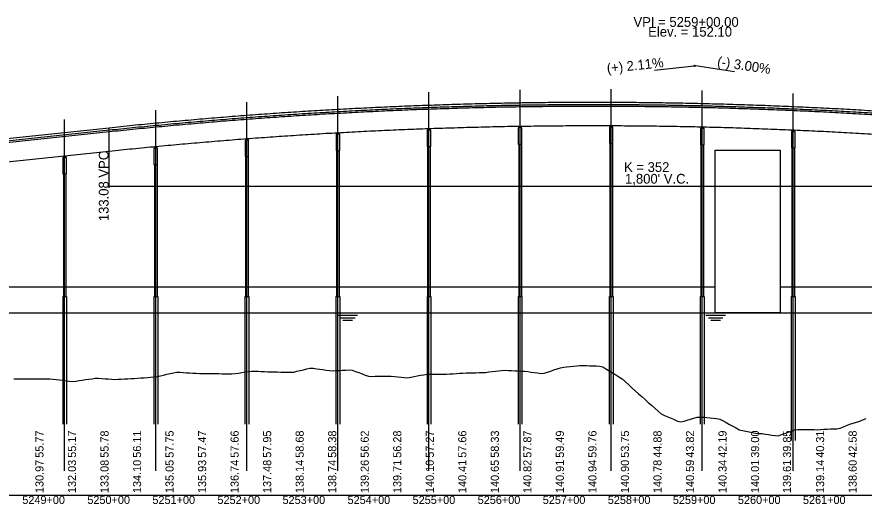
# Model space of a CAD drawing. Extents: x 2121671 to 2169879, y 557274 to 599957.
# Drawn here: x 2154426 to 2155728, y 579173 to 579923 of the extents above; entities that cross this region are included whole.
import ezdxf

# ---------------------------------------------------------------- set-up
doc = ezdxf.new("R2010")
doc.units = 0
for name, color, linetype in [('BR_CENTER LINES', 7, 'Continuous'), ('BR_CONCRETE', 7, 'Continuous'), ('BR_DETAILS', 7, 'Continuous'), ('BR_PRESTRESSED BEAM', 7, 'Continuous'), ('RD_DDB_GradeTX', 7, 'Continuous'), ('RD_DDB_Profile_Elev', 7, 'Continuous'), ('RD_DDB_Profile_EX', 7, 'Continuous'), ('RD_DDB_Profile_Lbl', 7, 'Continuous'), ('RD_DDB_Profile_PR', 7, 'Continuous'), ('RD_DDB_StaTX', 7, 'Continuous'), ('RD_DDB_StripGrade', 7, 'Continuous'), ('RD_DDB_VCLbl', 7, 'Continuous'), ('RD_GPK_Profile_Cell', 7, 'Continuous')]:
    doc.layers.add(name, color=color, linetype=linetype)

msp = doc.modelspace()

# ---------------------------------------------------------------- linework, layer by layer
at = {"layer": 'BR_CENTER LINES'}
for p, q in [((2155339.4, 579224.3), (2155339.4, 579811.5)), ((2154919.4, 579224.3), (2154919.4, 579800.6)), ((2155059.4, 579224.3), (2155059.4, 579807)), ((2155199.4, 579224.3), (2155199.4, 579810.6)), ((2155479.4, 579224.3), (2155479.4, 579809.5)), ((2155619.4, 579224.3), (2155619.4, 579804.8)), ((2154779.4, 579224.3), (2154779.4, 579791.4)), ((2154639.4, 579224.3), (2154639.4, 579779.4)), ((2154499.4, 579224.3), (2154499.4, 579765))]:
    msp.add_line(p, q, dxfattribs=at)
at = {"layer": 'BR_CONCRETE'}
for p, q in [((2154274.9, 579717.8), (2154567.9, 579748.7)), ((2155057.4, 579723.4), (2155057.4, 579492.4)), ((2155061.4, 579723.4), (2155061.4, 579492.4)), ((2155197.4, 579727.1), (2155197.4, 579492.4)), ((2155201.4, 579727.1), (2155201.4, 579492.4)), ((2155337.4, 579727.9), (2155337.4, 579492.4)), ((2155341.4, 579727.9), (2155341.4, 579492.4)), ((2155477.4, 579726), (2155477.4, 579492.4)), ((2155481.4, 579726), (2155481.4, 579492.4)), ((2155617.4, 579721.2), (2155617.4, 579492.4)), ((2155621.4, 579721.2), (2155621.4, 579492.4)), ((2154777.4, 579707.8), (2154777.4, 579492.4)), ((2154781.4, 579707.8), (2154781.4, 579492.4)), ((2154917.4, 579717), (2154917.4, 579492.4)), ((2154921.4, 579717), (2154921.4, 579492.4)), ((2154637.4, 579695.8), (2154637.4, 579492.4)), ((2154641.4, 579695.8), (2154641.4, 579492.4)), ((2154497.4, 579681.3), (2154497.4, 579492.4)), ((2154501.4, 579681.3), (2154501.4, 579492.4)), ((2154496.4, 579492.4), (2154496.4, 579296.1)), ((2154496.4, 579492.4), (2154502.4, 579492.4)), ((2154502.4, 579492.4), (2154502.4, 579296.1)), ((2154636.4, 579492.4), (2154636.4, 579296.1)), ((2154636.4, 579492.4), (2154642.4, 579492.4)), ((2154642.4, 579492.4), (2154642.4, 579296.1)), ((2154776.4, 579492.4), (2154776.4, 579296.1)), ((2154776.4, 579492.4), (2154782.4, 579492.4)), ((2154782.4, 579492.4), (2154782.4, 579296.1)), ((2154916.4, 579492.4), (2154916.4, 579296.1)), ((2154916.4, 579492.4), (2154922.4, 579492.4)), ((2154922.4, 579492.4), (2154922.4, 579296.1)), ((2155056.4, 579492.4), (2155056.4, 579296.1)), ((2155056.4, 579492.4), (2155062.4, 579492.4)), ((2155062.4, 579492.4), (2155062.4, 579296.1)), ((2155196.4, 579492.4), (2155196.4, 579296.1)), ((2155196.4, 579492.4), (2155202.4, 579492.4)), ((2155202.4, 579492.4), (2155202.4, 579296.1)), ((2155336.4, 579492.4), (2155336.4, 579296.1)), ((2155336.4, 579492.4), (2155342.4, 579492.4)), ((2155342.4, 579492.4), (2155342.4, 579296.1)), ((2155476.4, 579492.4), (2155476.4, 579296.1)), ((2155476.4, 579492.4), (2155482.4, 579492.4)), ((2155482.4, 579492.4), (2155482.4, 579296.1)), ((2155616.4, 579492.4), (2155616.4, 579271.3)), ((2155616.4, 579492.4), (2155622.4, 579492.4)), ((2155622.4, 579492.4), (2155622.4, 579271.3))]:
    msp.add_line(p, q, dxfattribs=at)
for points in [[(2155056.7, 579723.4), (2155062.2, 579723.4), (2155062.2, 579748.4), (2155056.7, 579748.4)], [(2155196.7, 579727.1), (2155202.2, 579727.1), (2155202.2, 579752.1), (2155196.7, 579752.1)], [(2155336.7, 579727.9), (2155342.2, 579727.9), (2155342.2, 579752.9), (2155336.7, 579752.9)], [(2155476.7, 579726), (2155482.2, 579726), (2155482.2, 579751), (2155476.7, 579751)], [(2154916.7, 579717), (2154922.2, 579717), (2154922.2, 579742), (2154916.7, 579742)], [(2155616.7, 579721.2), (2155622.2, 579721.2), (2155622.2, 579746.2), (2155616.7, 579746.2)], [(2154636.7, 579695.8), (2154642.2, 579695.8), (2154642.2, 579720.8), (2154636.7, 579720.8)], [(2154776.7, 579707.8), (2154782.2, 579707.8), (2154782.2, 579732.8), (2154776.7, 579732.8)], [(2154496.7, 579681.3), (2154502.2, 579681.3), (2154502.2, 579706.3), (2154496.7, 579706.3)]]:
    msp.add_lwpolyline(points, close=True, dxfattribs=at)
msp.add_spline([(2154567.9, 579748.7), (2154603.9, 579752.4), (2154639.9, 579755.9), (2154675.9, 579759.3), (2154711.9, 579762.4), (2154747.9, 579765.4), (2154783.9, 579768.2), (2154819.9, 579770.8), (2154855.9, 579773.2), (2154891.9, 579775.5), (2154927.9, 579777.5), (2154963.9, 579779.4), (2154999.9, 579781.1), (2155035.9, 579782.6), (2155071.9, 579783.9), (2155107.9, 579785), (2155143.9, 579786), (2155179.9, 579786.8), (2155215.9, 579787.3), (2155251.9, 579787.7), (2155287.9, 579787.9), (2155323.9, 579788), (2155359.9, 579787.8), (2155395.9, 579787.5), (2155431.9, 579787), (2155467.9, 579786.3), (2155503.9, 579785.4), (2155539.9, 579784.3), (2155575.9, 579783), (2155611.9, 579781.6), (2155647.9, 579780), (2155683.9, 579778.2), (2155719.9, 579776.2), (2155755.9, 579774), (2155791.9, 579771.6), (2155827.9, 579769.1), (2155863.9, 579766.3), (2155899.9, 579763.4), (2155935.9, 579760.3), (2155971.9, 579757), (2156007.9, 579753.6), (2156043.9, 579749.9), (2156079.9, 579746.1), (2156115.9, 579742.1), (2156151.9, 579737.9), (2156187.9, 579733.5), (2156223.9, 579728.9), (2156259.9, 579724.1), (2156295.9, 579719.2), (2156331.9, 579714.1), (2156367.9, 579708.8)], degree=3, dxfattribs=at)
at = {"layer": 'BR_DETAILS'}
for points in [[(2155057.9, 579750.9), (2155058.9, 579750.9), (2155058.9, 579748.4), (2155057.9, 579748.4)], [(2155059.9, 579750.9), (2155060.9, 579750.9), (2155060.9, 579748.4), (2155059.9, 579748.4)], [(2155197.9, 579754.6), (2155198.9, 579754.6), (2155198.9, 579752.1), (2155197.9, 579752.1)], [(2155199.9, 579754.6), (2155200.9, 579754.6), (2155200.9, 579752.1), (2155199.9, 579752.1)], [(2155337.9, 579755.4), (2155338.9, 579755.4), (2155338.9, 579752.9), (2155337.9, 579752.9)], [(2155339.9, 579755.4), (2155340.9, 579755.4), (2155340.9, 579752.9), (2155339.9, 579752.9)], [(2155477.9, 579753.5), (2155478.9, 579753.5), (2155478.9, 579751), (2155477.9, 579751)], [(2155479.9, 579753.5), (2155480.9, 579753.5), (2155480.9, 579751), (2155479.9, 579751)], [(2155617.9, 579748.7), (2155618.9, 579748.7), (2155618.9, 579746.2), (2155617.9, 579746.2)], [(2155619.9, 579748.7), (2155620.9, 579748.7), (2155620.9, 579746.2), (2155619.9, 579746.2)], [(2154777.9, 579735.3), (2154778.9, 579735.3), (2154778.9, 579732.8), (2154777.9, 579732.8)], [(2154779.9, 579735.3), (2154780.9, 579735.3), (2154780.9, 579732.8), (2154779.9, 579732.8)], [(2154917.9, 579744.5), (2154918.9, 579744.5), (2154918.9, 579742), (2154917.9, 579742)], [(2154919.9, 579744.5), (2154920.9, 579744.5), (2154920.9, 579742), (2154919.9, 579742)], [(2154637.9, 579723.3), (2154638.9, 579723.3), (2154638.9, 579720.8), (2154637.9, 579720.8)], [(2154639.9, 579723.3), (2154640.9, 579723.3), (2154640.9, 579720.8), (2154639.9, 579720.8)], [(2154497.9, 579708.8), (2154498.9, 579708.8), (2154498.9, 579706.3), (2154497.9, 579706.3)], [(2154499.9, 579708.8), (2154500.9, 579708.8), (2154500.9, 579706.3), (2154499.9, 579706.3)]]:
    msp.add_lwpolyline(points, close=True, dxfattribs=at)
at = {"layer": 'BR_PRESTRESSED BEAM'}
for p, q in [((2154274.9, 579715.3), (2154567.9, 579746.2)), ((2154359.4, 579694.2), (2154567.9, 579716.2))]:
    msp.add_line(p, q, dxfattribs=at)
for points in [[(2154567.9, 579746.2), (2154603.9, 579749.9), (2154639.9, 579753.4), (2154675.9, 579756.8), (2154711.9, 579759.9), (2154747.9, 579762.9), (2154783.9, 579765.7), (2154819.9, 579768.3), (2154855.9, 579770.7), (2154891.9, 579773), (2154927.9, 579775), (2154963.9, 579776.9), (2154999.9, 579778.6), (2155035.9, 579780.1), (2155071.9, 579781.4), (2155107.9, 579782.5), (2155143.9, 579783.5), (2155179.9, 579784.3), (2155215.9, 579784.8), (2155251.9, 579785.2), (2155287.9, 579785.4), (2155323.9, 579785.5), (2155359.9, 579785.3), (2155395.9, 579785), (2155431.9, 579784.5), (2155467.9, 579783.8), (2155503.9, 579782.9), (2155539.9, 579781.8), (2155575.9, 579780.5), (2155611.9, 579779.1), (2155647.9, 579777.5), (2155683.9, 579775.7), (2155719.9, 579773.7), (2155755.9, 579771.5), (2155791.9, 579769.1), (2155827.9, 579766.6), (2155863.9, 579763.8), (2155899.9, 579760.9), (2155935.9, 579757.8), (2155971.9, 579754.5), (2156007.9, 579751.1), (2156043.9, 579747.4), (2156079.9, 579743.6), (2156115.9, 579739.6), (2156151.9, 579735.4), (2156187.9, 579731), (2156223.9, 579726.4), (2156259.9, 579721.6), (2156295.9, 579716.7), (2156331.9, 579711.6), (2156367.9, 579706.3)], [(2154567.9, 579716.2), (2154603.9, 579719.9), (2154639.9, 579723.4), (2154675.9, 579726.8), (2154711.9, 579729.9), (2154747.9, 579732.9), (2154783.9, 579735.7), (2154819.9, 579738.3), (2154855.9, 579740.7), (2154891.9, 579743), (2154927.9, 579745), (2154963.9, 579746.9), (2154999.9, 579748.6), (2155035.9, 579750.1), (2155071.9, 579751.4), (2155107.9, 579752.5), (2155143.9, 579753.5), (2155179.9, 579754.3), (2155215.9, 579754.8), (2155251.9, 579755.2), (2155287.9, 579755.4), (2155323.9, 579755.5), (2155359.9, 579755.3), (2155395.9, 579755), (2155431.9, 579754.5), (2155467.9, 579753.8), (2155503.9, 579752.9), (2155539.9, 579751.8), (2155575.9, 579750.5), (2155611.9, 579749.1), (2155647.9, 579747.5), (2155683.9, 579745.7), (2155719.9, 579743.7), (2155755.9, 579741.5), (2155791.9, 579739.1), (2155827.9, 579736.6), (2155863.9, 579733.8), (2155899.9, 579730.9), (2155935.9, 579727.8), (2155971.9, 579724.5), (2156007.9, 579721.1), (2156043.9, 579717.4), (2156079.9, 579713.6), (2156115.9, 579709.6), (2156151.9, 579705.4), (2156187.9, 579701), (2156223.9, 579696.4), (2156259.9, 579691.6), (2156295.9, 579686.7), (2156331.9, 579681.6), (2156367.9, 579676.3)]]:
    msp.add_spline(points, degree=3, dxfattribs=at)
at = {"layer": 'RD_DDB_GradeTX'}
for p, q in [((2155406.3, 579840.8), (2155466.9, 579847.2)), ((2155529.2, 579838.1), (2155468.9, 579847.2))]:
    msp.add_line(p, q, dxfattribs=at)
msp.add_circle((2155467.9, 579847.3), 1, dxfattribs=at)
at = {"layer": 'RD_DDB_Profile_Elev'}
for p, q in [((2151922.4, 579507.4), (2155499.4, 579507.4)), ((2155599.4, 579507.4), (2156363.2, 579507.4)), ((2151953.5, 579467.4), (2156316.6, 579467.4)), ((2154919.6, 579463.7), (2154949.6, 579463.7)), ((2154923.4, 579459.9), (2154945.9, 579459.9)), ((2155485.2, 579463.7), (2155515.2, 579463.7)), ((2155488.9, 579459.9), (2155511.4, 579459.9)), ((2154927.1, 579456.2), (2154942.1, 579456.2)), ((2155492.7, 579456.2), (2155507.7, 579456.2))]:
    msp.add_line(p, q, dxfattribs=at)
msp.add_lwpolyline([(2155499.4, 579717.4), (2155599.4, 579717.4), (2155599.4, 579467.4), (2155499.4, 579467.4)], close=True, dxfattribs=at)
at = {"layer": 'RD_DDB_Profile_EX'}
for points in [[(2154721.5, 579374.1), (2154726.5, 579374), (2154731.5, 579374.1), (2154736.5, 579374), (2154741.5, 579373.9), (2154746.5, 579373.8), (2154751.5, 579373.7), (2154756.5, 579373.6), (2154761.5, 579374.1), (2154766.5, 579374.9), (2154771.5, 579375.7), (2154776.5, 579376.5), (2154781.5, 579377.3), (2154786.5, 579378), (2154791.5, 579377.7), (2154796.5, 579377.5), (2154801.5, 579377.2), (2154806.5, 579377), (2154811.5, 579376.8), (2154816.5, 579376.6), (2154821.5, 579376.5), (2154826.5, 579376.5), (2154831.5, 579376.4), (2154836.5, 579376.3), (2154841.5, 579376.3), (2154846.5, 579376.2), (2154851.5, 579376.3), (2154856.5, 579377.5), (2154861.5, 579378.7), (2154866.5, 579379.9), (2154871.5, 579381.1), (2154876.5, 579382.3), (2154881.5, 579382.2), (2154886.5, 579381.5), (2154891.5, 579380.8), (2154896.5, 579380.2), (2154901.5, 579379.5), (2154906.5, 579378.8), (2154911.5, 579378.3), (2154916.5, 579378.6), (2154921.5, 579378.9), (2154926.5, 579379.2), (2154931.5, 579379.5), (2154936.5, 579379.8), (2154941.5, 579379.2), (2154946.5, 579377.4), (2154951.5, 579375.5), (2154956.5, 579373.7), (2154961.5, 579371.8), (2154966.5, 579370), (2154971.5, 579369.8), (2154976.5, 579369.9), (2154981.5, 579370), (2154986.5, 579370), (2154991.5, 579370.1), (2154996.5, 579370.2), (2155001.5, 579369.9), (2155006.5, 579369.4), (2155011.5, 579368.9), (2155016.5, 579368.4), (2155021.5, 579367.8), (2155026.5, 579367.5), (2155031.5, 579368.5), (2155036.5, 579369.4), (2155041.5, 579370.4), (2155046.5, 579371.4), (2155051.5, 579372.3), (2155056.5, 579373.3), (2155061.5, 579373.2), (2155066.5, 579373.2), (2155071.5, 579373.1), (2155076.5, 579373.1), (2155081.5, 579373), (2155086.5, 579373.1), (2155091.5, 579373.4), (2155096.5, 579373.7), (2155101.5, 579374.1), (2155106.5, 579374.5), (2155111.5, 579374.8), (2155116.5, 579375.1), (2155121.5, 579375.2), (2155126.5, 579375.3), (2155131.5, 579375.4), (2155136.5, 579375.5), (2155141.5, 579375.6), (2155146.5, 579375.9), (2155151.5, 579376.5), (2155156.5, 579377.1), (2155161.5, 579377.7), (2155166.5, 579378.3), (2155171.5, 579378.9), (2155176.5, 579379.1), (2155181.5, 579378.9), (2155186.5, 579378.7), (2155191.5, 579378.5), (2155196.5, 579378.2), (2155201.5, 579378), (2155206.5, 579377.7), (2155211.5, 579377.1), (2155216.5, 579376.4), (2155221.5, 579375.7)], [(2155221.5, 579375.7), (2155226.5, 579375), (2155231.5, 579374.3), (2155236.5, 579374.6), (2155241.5, 579376.2), (2155246.5, 579377.9), (2155251.5, 579379.6), (2155256.5, 579381.2), (2155261.5, 579382.9), (2155266.5, 579384.1), (2155271.5, 579384.6), (2155276.5, 579385.1), (2155281.5, 579385.6), (2155286.5, 579386.1), (2155291.5, 579386.6), (2155296.5, 579386.7), (2155301.5, 579386.5), (2155306.5, 579386.2), (2155311.5, 579386), (2155316.5, 579385.7), (2155321.5, 579385.4), (2155326.5, 579384.2), (2155331.5, 579381.2), (2155336.5, 579378.2), (2155341.5, 579375.2), (2155346.5, 579372.2), (2155351.5, 579369.2), (2155356.5, 579366.1), (2155361.5, 579361.5), (2155366.5, 579356.9), (2155371.5, 579352.3), (2155376.5, 579347.7), (2155381.5, 579343.1), (2155386.5, 579338.7), (2155391.5, 579334.3), (2155396.5, 579329.8), (2155401.5, 579325.3), (2155406.5, 579320.8), (2155411.5, 579316.3), (2155416.5, 579311.9), (2155421.5, 579309.7), (2155426.5, 579307.6), (2155431.5, 579305.4), (2155436.5, 579303.2), (2155441.5, 579301.1), (2155446.5, 579299.6), (2155451.5, 579301.1), (2155456.5, 579302.6), (2155461.5, 579304), (2155466.5, 579305.5), (2155471.5, 579306.9), (2155476.5, 579307.2), (2155481.5, 579306.8), (2155486.5, 579306.3), (2155491.5, 579305.9), (2155496.5, 579305.4), (2155501.5, 579304.9), (2155506.5, 579304), (2155511.5, 579301.3), (2155516.5, 579298.6), (2155521.5, 579295.9), (2155526.5, 579293.1), (2155531.5, 579290.4), (2155536.5, 579287.5), (2155541.5, 579286.4), (2155546.5, 579285.3), (2155551.5, 579284.3), (2155556.5, 579283.3), (2155561.5, 579282.3), (2155566.5, 579281.9), (2155571.5, 579281.7), (2155576.5, 579280.9), (2155581.5, 579280.2), (2155586.5, 579279.4), (2155591.5, 579278.6), (2155596.5, 579278.5), (2155601.5, 579280.2), (2155606.5, 579282), (2155611.5, 579283.8), (2155616.5, 579285.6), (2155621.5, 579287.3), (2155626.5, 579287.9), (2155631.5, 579287.9), (2155636.5, 579287.9), (2155641.5, 579287.9), (2155646.5, 579287.9), (2155651.5, 579287.9), (2155656.5, 579287.6), (2155661.5, 579287.9), (2155666.5, 579288.3), (2155671.5, 579288.6), (2155676.5, 579289), (2155681.5, 579289.3), (2155686.5, 579289.1), (2155691.5, 579290.3), (2155696.5, 579292.2), (2155701.5, 579294.1), (2155706.5, 579296), (2155711.5, 579297.9), (2155716.5, 579299.3), (2155721.5, 579300.8)], [(2154421.5, 579366), (2154426.5, 579365.9), (2154431.5, 579365.8), (2154436.5, 579365.8), (2154441.5, 579365.7), (2154446.5, 579365.7), (2154451.5, 579365.7), (2154456.5, 579365.7), (2154461.5, 579365.7), (2154466.5, 579365.7), (2154471.5, 579365.7), (2154476.5, 579365.7), (2154481.5, 579365.2), (2154486.5, 579364.7), (2154491.5, 579364.2), (2154496.5, 579363.7), (2154501.5, 579363.1), (2154506.5, 579362.6), (2154511.5, 579362.1), (2154516.5, 579362.5), (2154521.5, 579363.2), (2154526.5, 579363.9), (2154531.5, 579364.7), (2154536.5, 579365.4), (2154541.5, 579366.1), (2154546.5, 579366.8), (2154551.5, 579366.9), (2154556.5, 579366.6), (2154561.5, 579366.2), (2154566.5, 579365.8), (2154571.5, 579365.5), (2154576.5, 579365.1), (2154581.5, 579365.2), (2154586.5, 579365.5), (2154591.5, 579365.8), (2154596.5, 579366), (2154601.5, 579366.3), (2154606.5, 579366.6), (2154611.5, 579366.9), (2154616.5, 579367.3), (2154621.5, 579367.7), (2154626.5, 579368.2), (2154631.5, 579368.6), (2154636.5, 579369.1), (2154641.5, 579369.5), (2154646.5, 579370.6), (2154651.5, 579371.8), (2154656.5, 579372.9), (2154661.5, 579374.1), (2154666.5, 579375.3), (2154671.5, 579376.3), (2154676.5, 579376), (2154681.5, 579375.7), (2154686.5, 579375.4), (2154691.5, 579375), (2154696.5, 579374.7), (2154701.5, 579374.5), (2154706.5, 579374.4), (2154711.5, 579374.3), (2154716.5, 579374.2), (2154721.5, 579374.1)], [(2155721.5, 579300.8), (2155726.5, 579302.8), (2155731.5, 579304.7)]]:
    msp.add_lwpolyline(points, dxfattribs=at)
at = {"layer": 'RD_DDB_Profile_PR'}
msp.add_line((2154274.9, 579721.3), (2154567.9, 579752.2), dxfattribs=at)
msp.add_spline([(2154567.9, 579752.2), (2154603.9, 579756), (2154639.9, 579759.5), (2154675.9, 579762.8), (2154711.9, 579766), (2154747.9, 579769), (2154783.9, 579771.8), (2154819.9, 579774.4), (2154855.9, 579776.8), (2154891.9, 579779), (2154927.9, 579781.1), (2154963.9, 579782.9), (2154999.9, 579784.6), (2155035.9, 579786.1), (2155071.9, 579787.4), (2155107.9, 579788.6), (2155143.9, 579789.5), (2155179.9, 579790.3), (2155215.9, 579790.9), (2155251.9, 579791.3), (2155287.9, 579791.5), (2155323.9, 579791.5), (2155359.9, 579791.4), (2155395.9, 579791), (2155431.9, 579790.5), (2155467.9, 579789.8), (2155503.9, 579788.9), (2155539.9, 579787.8), (2155575.9, 579786.6), (2155611.9, 579785.1), (2155647.9, 579783.5), (2155683.9, 579781.7), (2155719.9, 579779.7), (2155755.9, 579777.5), (2155791.9, 579775.2), (2155827.9, 579772.6), (2155863.9, 579769.9), (2155899.9, 579767), (2155935.9, 579763.9), (2155971.9, 579760.6), (2156007.9, 579757.1), (2156043.9, 579753.5), (2156079.9, 579749.6), (2156115.9, 579745.6), (2156151.9, 579741.4), (2156187.9, 579737), (2156223.9, 579732.4), (2156259.9, 579727.7), (2156295.9, 579722.7), (2156331.9, 579717.6), (2156367.9, 579712.3)], degree=3, dxfattribs=at)
at = {"layer": 'RD_DDB_VCLbl'}
for p, q in [((2154567.9, 579659.8), (2154567.9, 579752.2)), ((2154567.9, 579662.3), (2156367.9, 579662.3))]:
    msp.add_line(p, q, dxfattribs=at)
at = {"layer": 'RD_GPK_Profile_Cell'}
msp.add_line((2151067.9, 579186.8), (2157367.9, 579186.8), dxfattribs=at)

# ---------------------------------------------------------------- texts
at = {"layer": 'RD_DDB_GradeTX'}
for s, rotation, p in [('(+) 2.11%', 6.0299, (2155333.6, 579836.1)), ('(-) 3.00%', 351.4692, (2155501.8, 579846.9))]:
    msp.add_text(s, height=15, rotation=rotation, dxfattribs=at).set_placement(p)
at = {"layer": 'RD_DDB_Profile_Lbl'}
for s, p in [('VPI = 5259+00.00', (2155373.8, 579907.3)), ('Elev. = 152.10', (2155396.4, 579892.3))]:
    msp.add_text(s, height=15, dxfattribs=at).set_placement(p)
at = {"layer": 'RD_DDB_StaTX'}
for s, p in [('5249+00', (2154434.3, 579173.5)), ('5250+00', (2154534.3, 579173.5)), ('5251+00', (2154634.3, 579173.5)), ('5252+00', (2154734.3, 579173.5)), ('5253+00', (2154834.3, 579173.5)), ('5254+00', (2154934.3, 579173.5)), ('5255+00', (2155034.3, 579173.5)), ('5256+00', (2155134.3, 579173.5)), ('5257+00', (2155234.3, 579173.5)), ('5258+00', (2155334.3, 579173.5)), ('5259+00', (2155434.3, 579173.5)), ('5260+00', (2155534.3, 579173.5)), ('5261+00', (2155634.3, 579173.5))]:
    msp.add_text(s, height=12.5, dxfattribs=at).set_placement(p)
at = {"layer": 'RD_DDB_StripGrade'}
for s, height, p in [('133.08 VPC', 15, (2154566.9, 579608.5)), ('55.77', 12.5, (2154466.9, 579244.6)), ('55.17', 12.5, (2154516.9, 579244.6)), ('55.78', 12.5, (2154566.9, 579244.6)), ('56.11', 12.5, (2154616.9, 579244.6)), ('57.75', 12.5, (2154666.9, 579244.6)), ('57.47', 12.5, (2154716.9, 579244.6)), ('57.66', 12.5, (2154766.9, 579244.6)), ('57.95', 12.5, (2154816.9, 579244.6)), ('58.68', 12.5, (2154866.9, 579244.6)), ('58.38', 12.5, (2154916.9, 579244.6)), ('56.62', 12.5, (2154966.9, 579244.6)), ('56.28', 12.5, (2155016.9, 579244.6)), ('57.27', 12.5, (2155066.9, 579244.6)), ('57.66', 12.5, (2155116.9, 579244.6)), ('58.33', 12.5, (2155166.9, 579244.6)), ('57.87', 12.5, (2155216.9, 579244.6)), ('59.49', 12.5, (2155266.9, 579244.6)), ('59.76', 12.5, (2155316.9, 579244.6)), ('53.75', 12.5, (2155366.9, 579244.6)), ('44.88', 12.5, (2155416.9, 579244.6)), ('43.82', 12.5, (2155466.9, 579244.6)), ('42.19', 12.5, (2155516.9, 579244.6)), ('39.00', 12.5, (2155566.9, 579244.6)), ('39.85', 12.5, (2155616, 579244.6)), ('40.31', 12.5, (2155666.9, 579244.6)), ('42.58', 12.5, (2155716.9, 579244.6)), ('130.97', 12.5, (2154466.9, 579190.3)), ('132.03', 12.5, (2154516.9, 579190.3)), ('133.08', 12.5, (2154566.9, 579190.3)), ('134.10', 12.5, (2154616.9, 579190.3)), ('135.05', 12.5, (2154666.9, 579190.3)), ('135.93', 12.5, (2154716.9, 579190.3)), ('136.74', 12.5, (2154766.9, 579190.3)), ('137.48', 12.5, (2154816.9, 579190.3)), ('138.14', 12.5, (2154866.9, 579190.3)), ('138.74', 12.5, (2154916.9, 579190.3)), ('139.26', 12.5, (2154966.9, 579190.3)), ('139.71', 12.5, (2155016.9, 579190.3)), ('140.10', 12.5, (2155066.9, 579190.3)), ('140.41', 12.5, (2155116.9, 579190.3)), ('140.65', 12.5, (2155166.9, 579190.3)), ('140.82', 12.5, (2155216.9, 579190.3)), ('140.91', 12.5, (2155266.9, 579190.3)), ('140.94', 12.5, (2155316.9, 579190.3)), ('140.90', 12.5, (2155366.9, 579190.3)), ('140.78', 12.5, (2155416.9, 579190.3)), ('140.59', 12.5, (2155466.9, 579190.3)), ('140.34', 12.5, (2155516.9, 579190.3)), ('140.01', 12.5, (2155566.9, 579190.3)), ('139.61', 12.5, (2155616, 579190.3)), ('139.14', 12.5, (2155666.9, 579190.3)), ('138.60', 12.5, (2155716.9, 579190.3))]:
    msp.add_text(s, height=height, rotation=90, dxfattribs=at).set_placement(p)
at = {"layer": 'RD_DDB_VCLbl'}
for s, p in [('K = 352', (2155359.3, 579684.1)), ("1,800' V.C.", (2155360.8, 579666.2))]:
    msp.add_text(s, height=15, dxfattribs=at).set_placement(p)

doc.saveas('drawing.dxf')
